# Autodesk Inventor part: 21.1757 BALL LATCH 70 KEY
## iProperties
Created: 2007-03
Part Number: 21.1757 BALL LATCH 70 KEY
Document SubType Name: Modeling
Designer: Andy Moles
Material: Steel
Density: 7.85 g/cm^3
Author: Andy Moles
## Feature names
1. Extrusion1
2. Extrusion2
3. Hole1
4. Hole2
